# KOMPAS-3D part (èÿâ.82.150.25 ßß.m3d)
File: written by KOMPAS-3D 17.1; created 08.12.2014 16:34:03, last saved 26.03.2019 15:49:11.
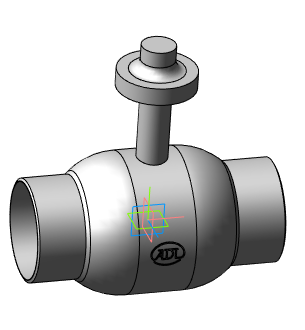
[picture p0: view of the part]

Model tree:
1. Операция без истории:6  (labels: Сталь 20  ГОСТ 1050-88)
